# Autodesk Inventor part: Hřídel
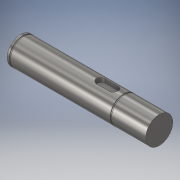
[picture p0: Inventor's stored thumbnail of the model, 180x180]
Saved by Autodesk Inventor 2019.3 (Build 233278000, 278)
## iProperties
Created: 2019-02
Part Number: Hřídel
Material: Ocel, legovaná
Document SubType Name: Modeling
Designer: B-hon
Density: 7.73 g/cm^3
Appearance: Pololeštěná
Mass: 450.073 g
Surface Area: 107.417 cm^2
Volume: 58.2242 cm^3
Author: B-hon
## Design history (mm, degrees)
sketch "Náčrt1"
  geometry: L1 (0, 0)-(103.236, 0) reference; L2 (0, 0)-(0, 12.5); L3 (100, 12.5)-(100, 0); L4 (3.1, 12.5)-(3.1, 11.95); L5 (3.1, 11.95)-(1.8, 11.95); L6 (1.8, 11.95)-(1.8, 12.5); L7 (0, 12.5)-(1.8, 12.5); L8 (96.4, 12.5)-(96.4, 11.95); L9 (96.4, 11.95)-(95.1, 11.95); L10 (95.1, 11.95)-(95.1, 12.5); L11 (3.1, 12.5)-(95.1, 12.5); L12 (96.4, 12.5)-(100, 12.5)
  constraints: 24 end point, 4 perpendicular, 2 horizontal, 2 parallel, 1 point on line, 1 vertical
  dimensions: "d0" = 100 distance of L2.end L3.start; "d2" = 1.8 distance between parallel lines of L2 L6; "d3" = 1.3 distance of L4.end L5.end; "d4" = 23.9 diameter of L5 L1; "d5" = 23.9 diameter of L9 L1; "d6" = 92 distance between parallel lines of L10 L4; "d7" = 1.3 distance of L8.end L9.end
revolve "Rotace1" sketch "Náčrt1" stored, may be unused: angle "d8" = 90 deg
node "Pracovní rovina1"
sketch "Náčrt2"
  geometry: L1 (-25, 0)-(-37, 0); L2 (-25, 4)-(-37, 4); L3 (-37, -4)-(-25, -4); L4 (-46, 12.5)-(-46, -12.5) reference; A1 r 4 centre (-25, 0) between (-25, -4) and (-25, 4); A2 r 4 centre (-37, 0) between (-37, 4) and (-37, -4); 2 further points
  constraints: 8 end point, 4 point on circle, 4 tangent, 2 centre point, 1 horizontal, 1 horizontal alignment, 1 midpoint, 1 parallel
  dimensions: "d9" = 8 diameter of A2; "d10" = 12 distance of L1.end L1.start; "d11" = 9 distance from line of L4 L1.end
extrude "Vysunutí1" cut sketch "Náčrt2" distance "d12" = 4.1; taper "d13" = 0 deg
node "Upravit přímo1"
node "Těleso1"
feature "Posunout1" dims "d16" = 28
other parameters: "d1" = 25, "d14" = 0, "d15" = 0
